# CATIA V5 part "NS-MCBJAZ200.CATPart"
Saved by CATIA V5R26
Part number: NS-MCBJAZ200
Bounding box of the stored display mesh (mm): x -70.94 to 158, y -249.867 to 0, z -71 to 71
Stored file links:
  R:\Document\坂尻\その他\ナベヤデータ変換\安全カバーキャスター\MCBJSAZ200\NS-MCBJAZ200.CATPart
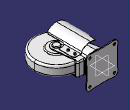
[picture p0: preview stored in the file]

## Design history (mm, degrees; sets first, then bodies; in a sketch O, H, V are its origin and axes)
Body1 (main body)
  Solid1: solid without history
